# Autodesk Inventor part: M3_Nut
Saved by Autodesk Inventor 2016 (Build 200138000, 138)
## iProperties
Created: 2015-11
Part Number: M3_Nut
Material: Generic
Document SubType Name: Modeling
Designer: John
Density: 1 g/cm^3
Appearance: Default
Author: John
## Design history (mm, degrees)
feature "Base1"
body "Solid1"
